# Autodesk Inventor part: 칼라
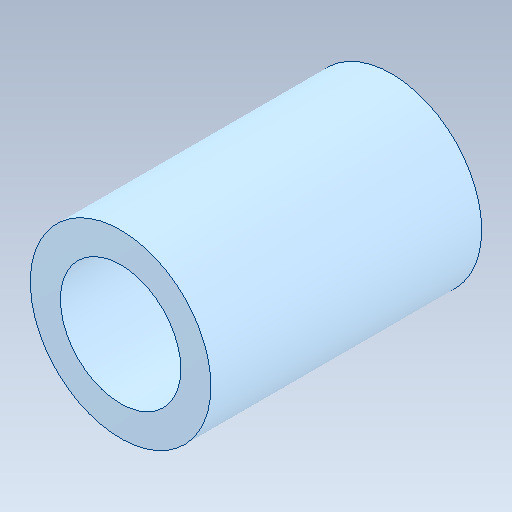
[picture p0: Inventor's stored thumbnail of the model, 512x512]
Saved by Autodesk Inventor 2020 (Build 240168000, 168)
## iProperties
Created: 2024-04
Part Number: 칼라
Material: 강철, 탄소
Document SubType Name: Modeling
Designer: oem
Density: 7.87 g/cm^3
Appearance: 기본값
Mass: 8.90076 g
Surface Area: 12.5664 cm^2
Volume: 1.13097 cm^3
Sending System: Autodesk Inventor 2025
Preprocessor: ST-DEVELOPER v20
Author: jhkim
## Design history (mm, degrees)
feature "솔리드1"
node "솔리드2"
